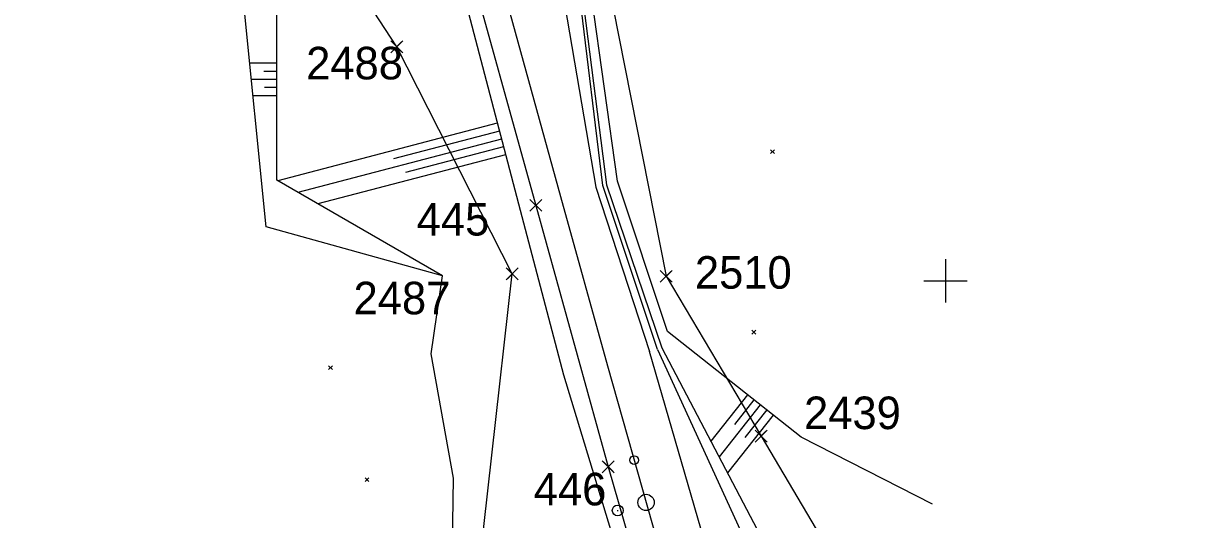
# Model space of a CAD drawing. Extents: x -866402 to -860377, y -1041908 to -1038598.
# Drawn here: x -864985 to -864876.8, y -1041022 to -1040976.3 of the extents above; entities that cross this region are included whole.
import ezdxf

# ---------------------------------------------------------------- set-up
doc = ezdxf.new("R2010")
doc.units = 0
for name, color, linetype in [('PS 02 trasa', 7, 'Continuous'), ('SZDC', 7, 'Continuous'), ('Vrstva 1', 7, 'Continuous'), ('Vrstva 48', 7, 'Continuous'), ('Vrstva 49', 7, 'Continuous'), ('Vrstva 5', 7, 'Continuous'), ('Vrstva 60', 7, 'Continuous'), ('Vrstva 7', 7, 'Continuous')]:
    doc.layers.add(name, color=color, linetype=linetype)

msp = doc.modelspace()

# ---------------------------------------------------------------- linework, layer by layer
at = {"layer": 'PS 02 trasa'}
msp.add_lwpolyline([(-864964.74, -1040896.52), (-864962.92, -1040903.11), (-864962.71, -1040910.62), (-864961.22, -1040914.56), (-864958.74, -1040918.21), (-864958.37, -1040919.54), (-864952.05, -1040942.22), (-864949.96, -1040949.05), (-864944.56, -1040968.56), (-864937.77, -1040993.04), (-864931.09, -1041017.13), (-864924.15, -1041041.22), (-864915.94, -1041065.03), (-864905.48, -1041088.03), (-864892.61, -1041109.78), (-864877.63, -1041129.41)], dxfattribs=at)
at = {"layer": 'SZDC'}
for points in [[(-864889.69, -1041132.82), (-864908.77, -1041095.23), (-864910.13, -1041091.21), (-864915.37, -1041075.7), (-864939.71, -1041049.14), (-864940.88, -1041044.32), (-864943.71, -1041032.76), (-864939.94, -1040999.35), (-864950.59, -1040978.43), (-864965.06, -1040956.29), (-864972.33, -1040948.55), (-864965.46, -1040904.57), (-864985, -1040866.09)], [(-864953.81, -1040886.99), (-864953.18, -1040911.04), (-864934.86, -1040933.14), (-864931.2, -1040972.04), (-864925.76, -1040999.58), (-864917, -1041014.31), (-864911.11, -1041024.22), (-864908.58, -1041028.48), (-864907.93, -1041036.91), (-864907.5, -1041042.63), (-864905.91, -1041063.49), (-864876.02, -1041096.59), (-864875.01, -1041097.53), (-864834, -1041135.62)]]:
    msp.add_lwpolyline(points, dxfattribs=at)
at = {"layer": 'Vrstva 1'}
msp.add_lwpolyline([(-864982.9, -1040820.53), (-864978.47, -1040836.58), (-864974.17, -1040852.14), (-864970.33, -1040866), (-864958.15, -1040909.99), (-864954.34, -1040923.87), (-864947.54, -1040948.55), (-864935.48, -1040992.22), (-864931.16, -1041007.84), (-864926.56, -1041024.11)], dxfattribs=at)
msp.add_circle((-864928.71, -1041016.51), 0.4, dxfattribs=at)
at = {"layer": 'Vrstva 48'}
for p, q in [((-864961.65, -1040979.94), (-864964.13, -1040979.95)), ((-864961.65, -1040981.44), (-864963.98, -1040981.45)), ((-864961.65, -1040980.69), (-864962.85, -1040980.7)), ((-864961.65, -1040982.19), (-864962.78, -1040982.19)), ((-864961.65, -1040982.94), (-864963.83, -1040982.95)), ((-864941.32, -1040985.48), (-864961.56, -1040990.77)), ((-864940.94, -1040986.93), (-864959.71, -1040991.84)), ((-864941.13, -1040986.2), (-864950.88, -1040988.76)), ((-864940.75, -1040987.66), (-864949.77, -1040990.02)), ((-864940.56, -1040988.38), (-864957.86, -1040992.91)), ((-864918.24, -1041010.5), (-864921.64, -1041014.78)), ((-864917.07, -1041011.43), (-864920.87, -1041016.23)), ((-864917.66, -1041010.96), (-864919.46, -1041013.23)), ((-864916.48, -1041011.89), (-864918.49, -1041014.43)), ((-864915.89, -1041012.36), (-864920.11, -1041017.68))]:
    msp.add_line(p, q, dxfattribs=at)
at = {"layer": 'Vrstva 49'}
for p, q in [((-864962.64, -1040995.03), (-864966.55, -1040955.5)), ((-864961.64, -1040990.72), (-864961.66, -1040955.98)), ((-864916.12, -1040987.91), (-864915.77, -1040988.27)), ((-864916.12, -1040988.27), (-864915.77, -1040987.91)), ((-864946.38, -1040999.54), (-864961.64, -1040990.72)), ((-864926.56, -1041006.33), (-864931.6, -1040991.22)), ((-864931.24, -1040991.15), (-864926.14, -1041006.18)), ((-864946.38, -1040999.54), (-864962.64, -1040995.03)), ((-864917.84, -1041004.55), (-864917.49, -1041004.91)), ((-864917.84, -1041004.91), (-864917.49, -1041004.55)), ((-864926.56, -1041006.33), (-864913.63, -1041034.47)), ((-864956.87, -1041007.82), (-864956.51, -1041008.17)), ((-864956.87, -1041008.17), (-864956.51, -1041007.82)), ((-864953.51, -1041018.15), (-864953.15, -1041018.5)), ((-864953.51, -1041018.5), (-864953.15, -1041018.15))]:
    msp.add_line(p, q, dxfattribs=at)
for points in [[(-864964.01, -1040904.16), (-864962.46, -1040910.1), (-864950.57, -1040950.12), (-864939.22, -1040993.49), (-864935.22, -1041008.65), (-864930.16, -1041025.34), (-864924.59, -1041042.51), (-864920.43, -1041060.05), (-864917.14, -1041066.1), (-864915.5, -1041072.18), (-864914.87, -1041074.9)], [(-864931.6, -1040991.22), (-864933.72, -1040973.73), (-864934.17, -1040962.93), (-864935.8, -1040947.92)], [(-864925.62, -1041004.65), (-864930.25, -1040990.81), (-864932.63, -1040973.69), (-864933.46, -1040961.59), (-864935.13, -1040947.93)], [(-864933.86, -1040962.64), (-864933.49, -1040973.57), (-864931.24, -1040991.15)], [(-864935.08, -1040974.61), (-864932.25, -1040991.36), (-864927.29, -1041006.52)], [(-864939.49, -1041039.12), (-864945.52, -1041028.43), (-864945.35, -1041018.17), (-864947.42, -1041006.72), (-864946.38, -1040999.54)], [(-864901.19, -1041020.58), (-864913.31, -1041014.41), (-864925.62, -1041004.65)], [(-864926.14, -1041006.18), (-864917.37, -1041022.91), (-864912.59, -1041034.25), (-864911.47, -1041038.29)], [(-864920.23, -1041033.14), (-864920.12, -1041031.96), (-864922.56, -1041022.83), (-864927.29, -1041006.52)]]:
    msp.add_lwpolyline(points, dxfattribs=at)
at = {"layer": 'Vrstva 5'}
for p, q in [((-864900, -1040998), (-864900, -1041002)), ((-864902, -1041000), (-864898, -1041000))]:
    msp.add_line(p, q, dxfattribs=at)
at = {"layer": 'Vrstva 60'}
for p, q in [((-864950.14, -1040978.88), (-864951.14, -1040977.88)), ((-864950.14, -1040977.98), (-864951.14, -1040978.98)), ((-864951.04, -1040978.88), (-864950.04, -1040977.88)), ((-864951.04, -1040977.98), (-864950.04, -1040978.98)), ((-864950.59, -1040978.43), (-864950.59, -1040978.43)), ((-864937.32, -1040993.49), (-864938.32, -1040992.49)), ((-864937.32, -1040992.59), (-864938.32, -1040993.59)), ((-864938.22, -1040993.49), (-864937.22, -1040992.49)), ((-864938.22, -1040992.59), (-864937.22, -1040993.59)), ((-864937.77, -1040993.04), (-864937.77, -1040993.04)), ((-864939.49, -1040999.8), (-864940.49, -1040998.8)), ((-864939.49, -1040998.9), (-864940.49, -1040999.9)), ((-864940.39, -1040999.8), (-864939.39, -1040998.8)), ((-864940.39, -1040998.9), (-864939.39, -1040999.9)), ((-864939.94, -1040999.35), (-864939.94, -1040999.35)), ((-864925.31, -1041000.03), (-864926.31, -1040999.03)), ((-864925.31, -1040999.13), (-864926.31, -1041000.13)), ((-864926.21, -1041000.03), (-864925.21, -1040999.03)), ((-864926.21, -1040999.13), (-864925.21, -1041000.13)), ((-864925.76, -1040999.58), (-864925.76, -1040999.58)), ((-864916.55, -1041014.76), (-864917.55, -1041013.76)), ((-864916.55, -1041013.86), (-864917.55, -1041014.86)), ((-864917.45, -1041014.76), (-864916.45, -1041013.76)), ((-864917.45, -1041013.86), (-864916.45, -1041014.86)), ((-864917, -1041014.31), (-864917, -1041014.31)), ((-864930.64, -1041017.58), (-864931.64, -1041016.58)), ((-864930.64, -1041016.68), (-864931.64, -1041017.68)), ((-864931.54, -1041017.58), (-864930.54, -1041016.58)), ((-864931.54, -1041016.68), (-864930.54, -1041017.68)), ((-864931.09, -1041017.13), (-864931.09, -1041017.13))]:
    msp.add_line(p, q, dxfattribs=at)
at = {"layer": 'Vrstva 7'}
msp.add_line((-864930.27, -1041021.16), (-864930.17, -1041021.16), dxfattribs=at)
for centre, radius in [((-864927.6, -1041020.42), 0.75), ((-864930.22, -1041021.16), 0.5)]:
    msp.add_circle(centre, radius, dxfattribs=at)

# ---------------------------------------------------------------- texts
at = {"layer": 'Vrstva 60'}
for s, p in [('2488', (-864958.94, -1040981.43)), ('445', (-864948.75, -1040995.82)), ('2510', (-864923.1, -1041000.72)), ('2487', (-864954.57, -1041003.08)), ('2439', (-864913.04, -1041013.66)), ('446', (-864937.96, -1041020.69))]:
    msp.add_text(s, height=3, dxfattribs=at).set_placement(p)

doc.saveas('drawing.dxf')
